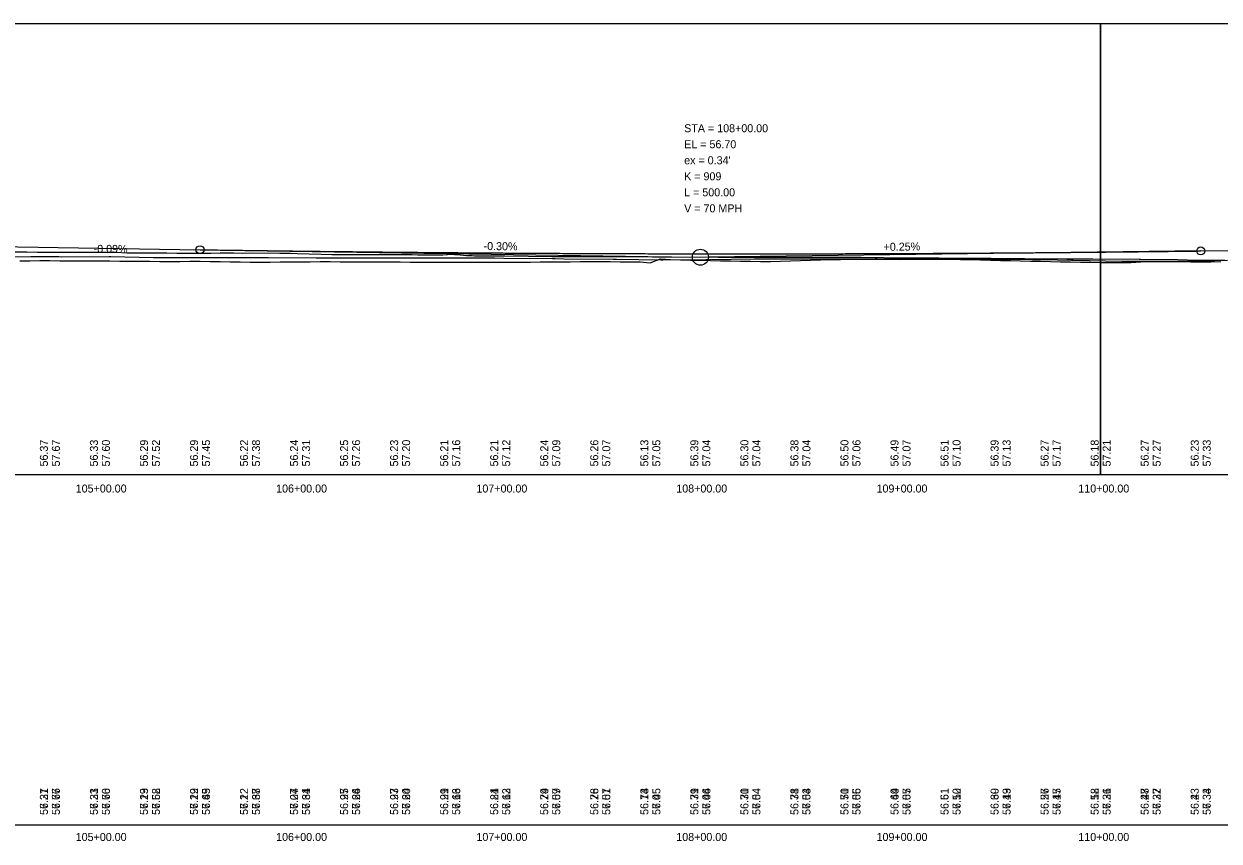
# Model space of a CAD drawing. Extents: x 3880794 to 3915434, y 287517 to 300173.
# Drawn here: x 3891000 to 3891597, y 297716 to 298124 of the extents above; entities that cross this region are included whole.
import ezdxf

# ---------------------------------------------------------------- set-up
doc = ezdxf.new("R2010")
doc.units = 0
for name, color, linetype in [('Level 1', 7, 'Continuous'), ('Level 2', 7, 'Continuous'), ('Level 30', 7, 'Continuous'), ('Level 31', 7, 'Continuous'), ('Level 32', 7, 'Continuous'), ('Level 62', 7, 'Continuous'), ('Level 63', 7, 'Continuous')]:
    doc.layers.add(name, color=color, linetype=linetype)

msp = doc.modelspace()

# ---------------------------------------------------------------- linework, layer by layer
at = {"layer": 'Level 1'}
for p, q in [((3890888.3, 298014.44), (3891088.3, 298011.44)), ((3891088.3, 298011.44), (3891334.3, 298007.75)), ((3891588.3, 298010.82), (3891342.3, 298007.74)), ((3891588.3, 298010.82), (3891688.3, 298012.07))]:
    msp.add_line(p, q, dxfattribs=at)
for points in [[(3890993.25, 298010.34), (3891001.84, 298010.31), (3891007.06, 298010.28), (3891023.83, 298010.16), (3891027.36, 298010.16), (3891030.67, 298010.28), (3891046.08, 298010.19), (3891051.84, 298009.85), (3891067.15, 298009.84), (3891071.65, 298009.86), (3891076.77, 298009.77), (3891093.63, 298009.79), (3891098.45, 298009.87), (3891105.07, 298009.82), (3891109.73, 298009.7), (3891114.75, 298009.85), (3891128.11, 298009.75), (3891133.4, 298009.65), (3891136.83, 298009.57), (3891148.78, 298009.14), (3891154.16, 298008.98), (3891171.21, 298009.09), (3891175.91, 298009.09), (3891180.21, 298008.98), (3891189.87, 298009.04), (3891194.26, 298009.01), (3891197.18, 298008.85), (3891200.87, 298008.93), (3891203.72, 298008.88), (3891206.7, 298008.93), (3891209.66, 298008.91), (3891211.91, 298009.12), (3891214.42, 298009.16), (3891215.39, 298009.11), (3891216.8, 298009.03), (3891221.39, 298008.61), (3891224.26, 298008.53), (3891225.37, 298008.46), (3891237.82, 298008.39), (3891239.57, 298008.31), (3891240.63, 298008.33), (3891264.08, 298008.12)], [(3891264.08, 298008.12), (3891265.34, 298008.11), (3891268.29, 298008.1), (3891291.17, 298008.08), (3891293.22, 298008.07), (3891294.11, 298008.06), (3891314.38, 298007.88), (3891315.96, 298007.86), (3891322.07, 298007.84), (3891323.88, 298007.8), (3891347.26, 298007.73), (3891347.58, 298007.73), (3891360.04, 298007.73), (3891361.56, 298007.74), (3891384.81, 298007.74), (3891386.73, 298007.74), (3891388.59, 298007.74), (3891411.54, 298007.72), (3891413.73, 298007.73), (3891418.67, 298007.66), (3891441.44, 298007.34), (3891443.7, 298007.35), (3891457.68, 298007.3), (3891459.07, 298007.27), (3891482.66, 298007.2), (3891483.53, 298007.21), (3891499.23, 298007.09), (3891500.27, 298007.08), (3891521.34, 298006.92), (3891521.77, 298006.92), (3891532.54, 298006.84), (3891534.38, 298006.83), (3891557.46, 298006.65), (3891558.23, 298006.64), (3891576.72, 298006.47), (3891581.65, 298006.4), (3891600.37, 298006.29)]]:
    msp.add_lwpolyline(points, dxfattribs=at)
msp.add_circle((3891338.3, 298007.69), 4, dxfattribs=at)
msp.add_spline([(3891088.3, 298011.44), (3891098.3, 298011.29), (3891108.3, 298011.15), (3891118.3, 298011.02), (3891128.3, 298010.88), (3891138.3, 298010.76), (3891148.3, 298010.64), (3891158.3, 298010.53), (3891168.3, 298010.42), (3891178.3, 298010.31), (3891188.3, 298010.22), (3891198.3, 298010.12), (3891208.3, 298010.04), (3891218.3, 298009.96), (3891228.3, 298009.88), (3891238.3, 298009.81), (3891248.3, 298009.74), (3891258.3, 298009.68), (3891268.3, 298009.63), (3891278.3, 298009.58), (3891288.3, 298009.54), (3891298.3, 298009.5), (3891308.3, 298009.47), (3891318.3, 298009.45), (3891328.3, 298009.42), (3891338.3, 298009.41), (3891348.3, 298009.4), (3891358.3, 298009.4), (3891368.3, 298009.4), (3891378.3, 298009.4), (3891388.3, 298009.41), (3891398.3, 298009.43), (3891408.3, 298009.46), (3891418.3, 298009.48), (3891428.3, 298009.52), (3891438.3, 298009.56), (3891448.3, 298009.6), (3891458.3, 298009.66), (3891468.3, 298009.71), (3891478.3, 298009.77), (3891488.3, 298009.84), (3891498.3, 298009.91), (3891508.3, 298009.99), (3891518.3, 298010.08), (3891528.3, 298010.16), (3891538.3, 298010.26), (3891548.3, 298010.36), (3891558.3, 298010.47), (3891568.3, 298010.58), (3891578.3, 298010.69), (3891588.3, 298010.82)], degree=3, dxfattribs=at)
at = {"layer": 'Level 2'}
for p, q in [((3890994.01, 298007.96), (3891003.85, 298007.99)), ((3891003.85, 298007.99), (3891016.46, 298007.97)), ((3891016.46, 298007.97), (3891017.77, 298007.97)), ((3891017.77, 298007.97), (3891018.85, 298007.95)), ((3891018.85, 298007.95), (3891042.92, 298007.97)), ((3891042.92, 298007.97), (3891043.68, 298007.98)), ((3891043.68, 298007.98), (3891064.94, 298007.56)), ((3891064.94, 298007.56), (3891065.6, 298007.55)), ((3891065.6, 298007.55), (3891088.7, 298007.62)), ((3891088.7, 298007.62), (3891094.06, 298007.6)), ((3891094.06, 298007.6), (3891095.29, 298007.61)), ((3891095.29, 298007.61), (3891119.18, 298007.54)), ((3891119.18, 298007.54), (3891121.3, 298007.53)), ((3891121.3, 298007.53), (3891122.47, 298007.52)), ((3891122.47, 298007.52), (3891146.3, 298007.36)), ((3891146.3, 298007.36), (3891152.62, 298007.38)), ((3891152.62, 298007.38), (3891153.79, 298007.37)), ((3891153.79, 298007.37), (3891177.57, 298007.43)), ((3891177.57, 298007.43), (3891178.79, 298007.45)), ((3891178.79, 298007.45), (3891179.67, 298007.44)), ((3891179.67, 298007.44), (3891203.68, 298007.31)), ((3891203.68, 298007.31), (3891205.52, 298007.32)), ((3891205.52, 298007.32), (3891206.62, 298007.32)), ((3891206.62, 298007.32), (3891231.06, 298007.4)), ((3891231.06, 298007.4), (3891235.47, 298007.35)), ((3891235.47, 298007.35), (3891240.17, 298007.29)), ((3891240.17, 298007.29), (3891264.5, 298007)), ((3891264.5, 298007), (3891265.69, 298007.01)), ((3891265.69, 298007.01), (3891270.11, 298006.96)), ((3891270.11, 298006.96), (3891294.78, 298006.68)), ((3891294.78, 298006.68), (3891296.47, 298006.66)), ((3891296.47, 298006.66), (3891318.65, 298006.35)), ((3891318.65, 298006.35), (3891319.78, 298006.34)), ((3891319.78, 298006.34), (3891341.05, 298006.48)), ((3891341.05, 298006.48), (3891342.31, 298006.51)), ((3891342.31, 298006.51), (3891365.33, 298006.91)), ((3891365.33, 298006.91), (3891366.31, 298006.89)), ((3891366.31, 298006.89), (3891374.65, 298006.88)), ((3891374.65, 298006.88), (3891398.92, 298006.85)), ((3891398.92, 298006.85), (3891399.58, 298006.85)), ((3891399.58, 298006.85), (3891401.56, 298006.86)), ((3891401.56, 298006.86), (3891425.62, 298006.99)), ((3891425.62, 298006.99), (3891426.57, 298006.98)), ((3891426.57, 298006.98), (3891430.53, 298006.96)), ((3891430.53, 298006.96), (3891454.56, 298006.83)), ((3891454.56, 298006.83), (3891455.67, 298006.82)), ((3891455.67, 298006.82), (3891464.7, 298006.77)), ((3891464.7, 298006.77), (3891465.68, 298006.77)), ((3891465.68, 298006.77), (3891489.7, 298006.64)), ((3891489.7, 298006.64), (3891490.36, 298006.64)), ((3891490.36, 298006.64), (3891504.17, 298006.51)), ((3891504.17, 298006.51), (3891504.61, 298006.51)), ((3891504.61, 298006.51), (3891516.69, 298006.41)), ((3891516.69, 298006.41), (3891523.67, 298006.26)), ((3891523.67, 298006.26), (3891524.58, 298006.27)), ((3891524.58, 298006.27), (3891548.86, 298005.78)), ((3891548.86, 298005.78), (3891556.85, 298005.78)), ((3891556.85, 298005.78), (3891557.68, 298005.77)), ((3891557.68, 298005.77), (3891581.83, 298005.77)), ((3891581.83, 298005.77), (3891582.37, 298005.75)), ((3891582.37, 298005.75), (3891601.6, 298006.17))]:
    msp.add_line(p, q, dxfattribs=at)
for points in [[(3890998.3, 298005.91), (3891003.3, 298005.96), (3891008.3, 298006.11), (3891013.3, 298006.04), (3891018.3, 298005.96), (3891023.3, 298005.88), (3891028.3, 298005.81), (3891033.3, 298005.9), (3891038.3, 298005.86)], [(3891038.3, 298005.86), (3891043.3, 298005.82), (3891048.3, 298005.78), (3891053.3, 298005.73), (3891058.3, 298005.69), (3891063.3, 298005.64), (3891068.3, 298005.59), (3891073.3, 298005.61), (3891078.3, 298005.62), (3891083.3, 298005.64), (3891088.3, 298005.66), (3891093.3, 298005.57), (3891098.3, 298005.5), (3891103.3, 298005.43), (3891108.3, 298005.36), (3891113.3, 298005.29), (3891118.3, 298005.25), (3891123.3, 298005.29), (3891128.3, 298005.32), (3891133.3, 298005.36), (3891138.3, 298005.4), (3891143.3, 298005.44), (3891148.3, 298005.48), (3891153.3, 298005.47), (3891158.3, 298005.45), (3891163.3, 298005.43), (3891168.3, 298005.42), (3891173.3, 298005.4), (3891178.3, 298005.39), (3891183.3, 298005.36), (3891188.3, 298005.33), (3891193.3, 298005.3), (3891198.3, 298005.27), (3891203.3, 298005.24), (3891208.3, 298005.26), (3891213.3, 298005.25), (3891218.3, 298005.24), (3891223.3, 298005.22), (3891228.3, 298005.21), (3891233.3, 298005.19), (3891238.3, 298005.24), (3891243.3, 298005.26), (3891248.3, 298005.28), (3891253.3, 298005.3), (3891258.3, 298005.32), (3891263.3, 298005.4), (3891268.3, 298005.43), (3891273.3, 298005.46), (3891278.3, 298005.48), (3891283.3, 298005.51), (3891288.3, 298005.51), (3891293.3, 298005.47), (3891298.3, 298005.42), (3891303.3, 298005.38), (3891308.3, 298005.34), (3891313.3, 298004.84), (3891318.3, 298006.8), (3891323.3, 298006.59), (3891328.3, 298006.44), (3891333.3, 298006.29), (3891338.3, 298006.14), (3891343.3, 298006.02), (3891348.3, 298005.93), (3891353.3, 298005.85), (3891358.3, 298005.76), (3891363.3, 298005.68), (3891368.3, 298005.6), (3891373.3, 298005.55), (3891378.3, 298005.74), (3891383.3, 298005.92), (3891388.3, 298006.1), (3891393.3, 298006.27), (3891398.3, 298006.38), (3891403.3, 298006.49), (3891408.3, 298006.6), (3891413.3, 298006.72), (3891418.3, 298006.75), (3891423.3, 298006.72), (3891428.3, 298006.69), (3891433.3, 298006.66), (3891438.3, 298006.62), (3891443.3, 298006.65), (3891448.3, 298006.68), (3891453.3, 298006.72), (3891458.3, 298006.75), (3891463.3, 298006.72), (3891468.3, 298006.6), (3891473.3, 298006.47), (3891478.3, 298006.34), (3891483.3, 298006.24), (3891488.3, 298006.13), (3891493.3, 298006), (3891498.3, 298005.86), (3891503.3, 298005.73), (3891508.3, 298005.64), (3891513.3, 298005.54), (3891518.3, 298005.46), (3891523.3, 298005.36), (3891528.3, 298005.28), (3891533.3, 298005.18), (3891538.3, 298005.11)], [(3891538.3, 298005.11), (3891543.3, 298005.1), (3891548.3, 298005.09), (3891553.3, 298005.07), (3891558.3, 298005.31), (3891563.3, 298005.56), (3891568.3, 298005.63), (3891573.3, 298005.59), (3891578.3, 298005.56), (3891583.3, 298005.46), (3891588.3, 298005.36), (3891593.3, 298005.32), (3891598.3, 298005.47)]]:
    msp.add_lwpolyline(points, dxfattribs=at)
at = {"layer": 'Level 31'}
for centre in [(3891088.3, 298011.44), (3891588.3, 298010.82)]:
    msp.add_circle(centre, 2, dxfattribs=at)
at = {"layer": 'Level 62'}
for points in [[(3890838.3, 297899.19), (3891538.3, 297899.19), (3891538.3, 298124.19), (3890838.3, 298124.19)], [(3890838.3, 297899.19), (3891538.3, 297899.19), (3891538.3, 298124.19), (3890838.3, 298124.19)], [(3891538.3, 297899.19), (3892238.3, 297899.19), (3892238.3, 298124.19), (3891538.3, 298124.19)], [(3891538.3, 297899.19), (3892238.3, 297899.19), (3892238.3, 298124.19), (3891538.3, 298124.19)]]:
    msp.add_lwpolyline(points, close=True, dxfattribs=at)
at = {"layer": 'Level 63'}
msp.add_line((3881538.3, 297724.19), (3896411.35, 297724.19), dxfattribs=at)

# ---------------------------------------------------------------- texts
at = {"layer": 'Level 2'}
msp.add_text('-0.09%', height=4, rotation=359.74995, dxfattribs=at).set_placement((3891035.15, 298009.9))
at = {"layer": 'Level 30'}
for s, p in [('105+00.00', (3891026.2, 297890.19)), ('105+00.00', (3891026.2, 297890.19)), ('106+00.00', (3891126.33, 297890.19)), ('106+00.00', (3891126.33, 297890.19)), ('107+00.00', (3891226.42, 297890.19)), ('107+00.00', (3891226.42, 297890.19)), ('108+00.00', (3891326.27, 297890.19)), ('108+00.00', (3891326.27, 297890.19)), ('109+00.00', (3891426.33, 297890.19)), ('109+00.00', (3891426.33, 297890.19)), ('110+00.00', (3891527.15, 297890.19)), ('110+00.00', (3891527.15, 297890.19)), ('105+00.00', (3891026.2, 297716.19)), ('105+00.00', (3891026.2, 297716.19)), ('106+00.00', (3891126.33, 297716.19)), ('106+00.00', (3891126.33, 297716.19)), ('107+00.00', (3891226.42, 297716.19)), ('107+00.00', (3891226.42, 297716.19)), ('108+00.00', (3891326.27, 297716.19)), ('108+00.00', (3891326.27, 297716.19)), ('109+00.00', (3891426.33, 297716.19)), ('109+00.00', (3891426.33, 297716.19)), ('110+00.00', (3891527.15, 297716.19)), ('110+00.00', (3891527.15, 297716.19))]:
    msp.add_text(s, height=4, dxfattribs=at).set_placement(p)
at = {"layer": 'Level 31'}
for s, p in [('STA = 108+00.00', (3891330.21, 298070.1)), ('EL = 56.70', (3891330.21, 298062.1)), ("ex = 0.34'", (3891330.21, 298054.1)), ('K = 909', (3891330.21, 298046.1)), ('L = 500.00', (3891330.21, 298038.1)), ('V = 70 MPH', (3891330.21, 298030.1))]:
    msp.add_text(s, height=4, dxfattribs=at).set_placement(p)
for s, rotation, p in [('-0.30%', 359.14063, (3891229.96, 298011.32)), ('+0.25%', 0.71616, (3891429.86, 298010.84)), ('57.67', 90, (3891018.3, 297903.19)), ('57.60', 90, (3891043.3, 297903.19)), ('57.52', 90, (3891068.3, 297903.19)), ('57.45', 90, (3891093.3, 297903.19)), ('57.38', 90, (3891118.3, 297903.19)), ('57.31', 90, (3891143.3, 297903.19)), ('57.26', 90, (3891168.3, 297903.19)), ('57.20', 90, (3891193.3, 297903.19)), ('57.16', 90, (3891218.3, 297903.19)), ('57.12', 90, (3891243.3, 297903.19)), ('57.09', 90, (3891268.3, 297903.19)), ('57.07', 90, (3891293.3, 297903.19)), ('57.05', 90, (3891318.3, 297903.19)), ('57.04', 90, (3891343.3, 297903.19)), ('57.04', 90, (3891368.3, 297903.19)), ('57.04', 90, (3891393.3, 297903.19)), ('57.06', 90, (3891418.3, 297903.19)), ('57.07', 90, (3891443.3, 297903.19)), ('57.10', 90, (3891468.3, 297903.19)), ('57.13', 90, (3891493.3, 297903.19)), ('57.17', 90, (3891518.3, 297903.19)), ('57.21', 90, (3891543.3, 297903.19)), ('57.27', 90, (3891568.3, 297903.19)), ('57.33', 90, (3891593.3, 297903.19)), ('57.21', 90, (3891012.3, 297729.19)), ('57.67', 90, (3891018.3, 297729.19)), ('57.21', 90, (3891037.3, 297729.19)), ('57.60', 90, (3891043.3, 297729.19)), ('57.13', 90, (3891062.3, 297729.19)), ('57.52', 90, (3891068.3, 297729.19)), ('57.12', 90, (3891087.3, 297729.19)), ('57.45', 90, (3891093.3, 297729.19)), ('57.12', 90, (3891112.3, 297729.19)), ('57.38', 90, (3891118.3, 297729.19)), ('57.07', 90, (3891137.3, 297729.19)), ('57.31', 90, (3891143.3, 297729.19)), ('56.97', 90, (3891162.3, 297729.19)), ('57.26', 90, (3891168.3, 297729.19)), ('56.97', 90, (3891187.3, 297729.19)), ('57.20', 90, (3891193.3, 297729.19)), ('56.99', 90, (3891212.3, 297729.19)), ('57.16', 90, (3891218.3, 297729.19)), ('56.84', 90, (3891237.3, 297729.19)), ('57.12', 90, (3891243.3, 297729.19)), ('56.79', 90, (3891262.3, 297729.19)), ('57.09', 90, (3891268.3, 297729.19)), ('56.78', 90, (3891287.3, 297729.19)), ('57.07', 90, (3891293.3, 297729.19)), ('56.74', 90, (3891312.3, 297729.19)), ('57.05', 90, (3891318.3, 297729.19)), ('56.71', 90, (3891337.3, 297729.19)), ('57.04', 90, (3891343.3, 297729.19)), ('56.71', 90, (3891362.3, 297729.19)), ('57.04', 90, (3891368.3, 297729.19)), ('56.71', 90, (3891387.3, 297729.19)), ('57.04', 90, (3891393.3, 297729.19)), ('56.71', 90, (3891412.3, 297729.19)), ('57.06', 90, (3891418.3, 297729.19)), ('56.64', 90, (3891437.3, 297729.19)), ('57.07', 90, (3891443.3, 297729.19)), ('56.61', 90, (3891462.3, 297729.19)), ('57.10', 90, (3891468.3, 297729.19)), ('56.60', 90, (3891487.3, 297729.19)), ('57.13', 90, (3891493.3, 297729.19)), ('56.56', 90, (3891512.3, 297729.19)), ('57.17', 90, (3891518.3, 297729.19)), ('56.52', 90, (3891537.3, 297729.19)), ('57.21', 90, (3891543.3, 297729.19)), ('56.48', 90, (3891562.3, 297729.19)), ('57.27', 90, (3891568.3, 297729.19)), ('56.43', 90, (3891587.3, 297729.19)), ('57.33', 90, (3891593.3, 297729.19))]:
    msp.add_text(s, height=4, rotation=rotation, dxfattribs=at).set_placement(p)
at = {"layer": 'Level 32'}
for s, p in [('56.37', (3891012.3, 297903.19)), ('56.33', (3891037.3, 297903.19)), ('56.29', (3891062.3, 297903.19)), ('56.29', (3891087.3, 297903.19)), ('56.22', (3891112.3, 297903.19)), ('56.24', (3891137.3, 297903.19)), ('56.25', (3891162.3, 297903.19)), ('56.23', (3891187.3, 297903.19)), ('56.21', (3891212.3, 297903.19)), ('56.21', (3891237.3, 297903.19)), ('56.24', (3891262.3, 297903.19)), ('56.26', (3891287.3, 297903.19)), ('56.13', (3891312.3, 297903.19)), ('56.39', (3891337.3, 297903.19)), ('56.30', (3891362.3, 297903.19)), ('56.38', (3891387.3, 297903.19)), ('56.50', (3891412.3, 297903.19)), ('56.49', (3891437.3, 297903.19)), ('56.51', (3891462.3, 297903.19)), ('56.39', (3891487.3, 297903.19)), ('56.27', (3891512.3, 297903.19)), ('56.18', (3891537.3, 297903.19)), ('56.27', (3891562.3, 297903.19)), ('56.23', (3891587.3, 297903.19)), ('56.37', (3891012.3, 297729.19)), ('56.76', (3891018.3, 297729.19)), ('56.33', (3891037.3, 297729.19)), ('56.76', (3891043.3, 297729.19)), ('56.29', (3891062.3, 297729.19)), ('56.68', (3891068.3, 297729.19)), ('56.29', (3891087.3, 297729.19)), ('56.69', (3891093.3, 297729.19)), ('56.22', (3891112.3, 297729.19)), ('56.67', (3891118.3, 297729.19)), ('56.24', (3891137.3, 297729.19)), ('56.64', (3891143.3, 297729.19)), ('56.25', (3891162.3, 297729.19)), ('56.64', (3891168.3, 297729.19)), ('56.23', (3891187.3, 297729.19)), ('56.64', (3891193.3, 297729.19)), ('56.21', (3891212.3, 297729.19)), ('56.63', (3891218.3, 297729.19)), ('56.21', (3891237.3, 297729.19)), ('56.63', (3891243.3, 297729.19)), ('56.24', (3891262.3, 297729.19)), ('56.57', (3891268.3, 297729.19)), ('56.26', (3891287.3, 297729.19)), ('56.51', (3891293.3, 297729.19)), ('56.13', (3891312.3, 297729.19)), ('56.45', (3891318.3, 297729.19)), ('56.39', (3891337.3, 297729.19)), ('56.46', (3891343.3, 297729.19)), ('56.30', (3891362.3, 297729.19)), ('56.54', (3891368.3, 297729.19)), ('56.38', (3891387.3, 297729.19)), ('56.53', (3891393.3, 297729.19)), ('56.50', (3891412.3, 297729.19)), ('56.55', (3891418.3, 297729.19)), ('56.49', (3891437.3, 297729.19)), ('56.55', (3891443.3, 297729.19)), ('56.51', (3891462.3, 297729.19)), ('56.52', (3891468.3, 297729.19)), ('56.39', (3891487.3, 297729.19)), ('56.49', (3891493.3, 297729.19)), ('56.27', (3891512.3, 297729.19)), ('56.45', (3891518.3, 297729.19)), ('56.18', (3891537.3, 297729.19)), ('56.36', (3891543.3, 297729.19)), ('56.27', (3891562.3, 297729.19)), ('56.32', (3891568.3, 297729.19)), ('56.23', (3891587.3, 297729.19)), ('56.34', (3891593.3, 297729.19))]:
    msp.add_text(s, height=4, rotation=90, dxfattribs=at).set_placement(p)

doc.saveas('drawing.dxf')
